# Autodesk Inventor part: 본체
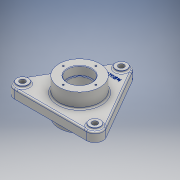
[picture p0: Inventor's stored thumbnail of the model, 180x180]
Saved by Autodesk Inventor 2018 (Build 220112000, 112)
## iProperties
Created: 2023-04
Part Number: 본체
Material: 알루미늄 6061
Document SubType Name: Modeling
Designer: 강의실04
Density: 2.7 g/cm^3
Appearance: 알루미늄 - 평지
Mass: 1219.15 g
Surface Area: 640.904 cm^2
Volume: 451.537 cm^3
Author: 강의실04
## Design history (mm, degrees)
sketch "스케치1"
  geometry: C1 r 40 at (0, 0); 1 further point
  constraints: 1 centre point, 1 coincident
  dimensions: "d0" = 80 diameter of C1
extrude "돌출1" new body sketch "스케치1" distance "d1" = 18; taper "d2" = 0 deg
sketch "스케치2"
  geometry: C1 r 45 at (0, 0); 1 further point
  constraints: 1 centre point, 1 coincident
  dimensions: "d3" = 90 diameter of C1
extrude "돌출2" join sketch "스케치2" distance "d4" = 5; taper "d5" = 0 deg
sketch "스케치3" dims "d6" = 114
  geometry: L1 (-98.727, -57)-(0, 114); L2 (0, 114)-(98.727, -57); L3 (98.727, -57)-(-98.727, -57); 4 further points
  constraints: 6 end point, 2 coincident, 1 midpoint, 1 vertical alignment, 9 other
extrude "돌출3" join sketch "스케치3" distance "d7" = 18; taper "d8" = 0 deg
sketch "스케치4"
  geometry: C1 r 40 at (0, 0) reference; C2 r 40 at (0, 0); 1 further point
  constraints: 1 centre point, 1 coincident
  dimensions: "d9" = 80 diameter of C2
extrude "돌출4" join sketch "스케치4" distance "d10" = 29; taper "d11" = 0 deg
sketch "스케치5"
  geometry: C1 r 21 at (0, 0); 1 further point
  constraints: 1 centre point, 1 coincident
  dimensions: "d12" = 42 diameter of C1
extrude "돌출5" cut sketch "스케치5" extent not by distance; stored distance "d13" = 29; taper "d14" = 0 deg
sketch "스케치6"
  geometry: C1 r 23.5 at (0, 0); 1 further point
  constraints: 1 centre point, 1 coincident
  dimensions: "d15" = 47 diameter of C1
extrude "돌출6" cut sketch "스케치6" distance "d16" = 17; taper "d17" = 0 deg
sketch "스케치7"
  geometry: C1 r 23.5 at (0, 0); 1 further point
  constraints: 1 centre point, 1 coincident
  dimensions: "d18" = 47 diameter of C1
extrude "돌출7" cut sketch "스케치7" distance "d19" = 17; taper "d20" = 0 deg
fillet "모깎기1" dims "d21" = 16
sketch "스케치8" dims "d22" = 164
  geometry: C1 r 11 at (0, 82); 2 further points
  constraints: 1 centre point, 1 coincident, 1 vertical alignment, 2 other
  dimensions: "d23" = 22 diameter of C1
extrude "돌출8" join sketch "스케치8" distance "d24" = 4; taper "d25" = 0 deg
sketch "스케치9"
  geometry: C1 r 5.5 at (0, 0); 1 further point
  constraints: 1 centre point
  dimensions: "d26" = 11 diameter of C1
extrude "돌출9" cut sketch "스케치9" extent not by distance; stored distance "d27" = 4; taper "d28" = 0 deg
sketch "스케치10" dims "d29" = 64
  geometry: 3 further points
  constraints: 2 vertical alignment, 1 coincident, 2 other
hole "구멍1" sketch "스케치10" at (0, 32) diameter "d30" = 3.242; stored, may be unused: countersink angle "d34" = 90 deg, drill point angle "d36" = 118 deg; dims "d31" = 8, "d32" = 9.4, "d33" = 2, "d35" = 10
sketch "스케치11"
  geometry: C1 r 32 at (0, 0); C2 r 1.621 at (0, 32) reference; 2 further points
  constraints: 2 coincident, 1 centre point
  dimensions: "d40" = 64 diameter of C1
hole "구멍2" sketch "스케치11" at (0, 32) diameter "d41" = 3.242; stored, may be unused: countersink angle "d45" = 90 deg, drill point angle "d47" = 118 deg; dims "d42" = 8, "d43" = 9.4, "d44" = 2, "d46" = 10
fillet "모깎기2" dims "d51" = 3
fillet "모깎기3" dims "d55" = 3
chamfer "모따기1" distance "d56" = 1; stored, may be unused: second distance "d57" = 2, angle "d58" = 45 deg
chamfer "모따기2" distance "d59" = 1; stored, may be unused: second distance "d60" = 2, angle "d61" = 45 deg
fillet "모깎기4" dims "d62" = 0.6
sketch "스케치12"
  geometry: 2 further points
  constraints: 1 vertical alignment, 1 other
  dimensions: "d66" = 60 distance of point (0, 0) point (0, 60)
feature "엠보싱2" sketch "스케치12" dims "d9" = 80, "d67" = 0.5, "d68" = 0
node "솔리드1"
pattern_circular "원형 패턴1" dims angle "d38" = 360 deg
pattern_circular "원형 패턴2" dims angle "d49" = 360 deg
pattern_circular "원형 패턴3" dims angle "d53" = 360 deg
